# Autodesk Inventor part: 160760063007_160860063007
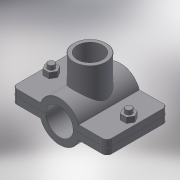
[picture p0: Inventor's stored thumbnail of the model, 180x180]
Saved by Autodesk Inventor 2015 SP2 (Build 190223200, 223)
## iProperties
Created: 2017-05
Part Number: 160760063007_160860063007
Material: Generic
Description: PLASSON SADDLE 63-3/4"
Document SubType Name: Modeling
Designer: KIM
Density: 1 g/cm^3
Appearance: Default
Author: KIM
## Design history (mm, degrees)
derived "16076.ipt"
feature "Solid1::16076.ipt"
feature "Solid2::16076.ipt"
tag "TaggingFeature1"
body "Solid1"
other parameters: "d0" = 78.75, "d1" = 116, "d2" = 31.5, "d3" = 63, "d4" = 84, "d5" = 0, "d6" = 5.8, "d7" = 116, "d8" = 0.1, "d10" = 0, "d11" = 0.63, "d14" = 31.3521, "d20" = 0.63, "d23" = 0.63, "d37" = 8, "d38" = 39.5, "d39" = 0, "d40" = 3, "d41" = 5, "d42" = 0, "d43" = 6, "d44" = 3, "d45" = 0, "d46" = 0.63, "d51" = 59, "d52" = 24.117, "d53" = 19, "d54" = 0, "d57" = 0, "d58" = 68.04, "d60" = 0, "d63" = 8, "d66" = 68, "d_" = 63, "G_" = 24.117, "A_" = 59, "L_" = 116, "L_1" = 84, "l_2" = 19
